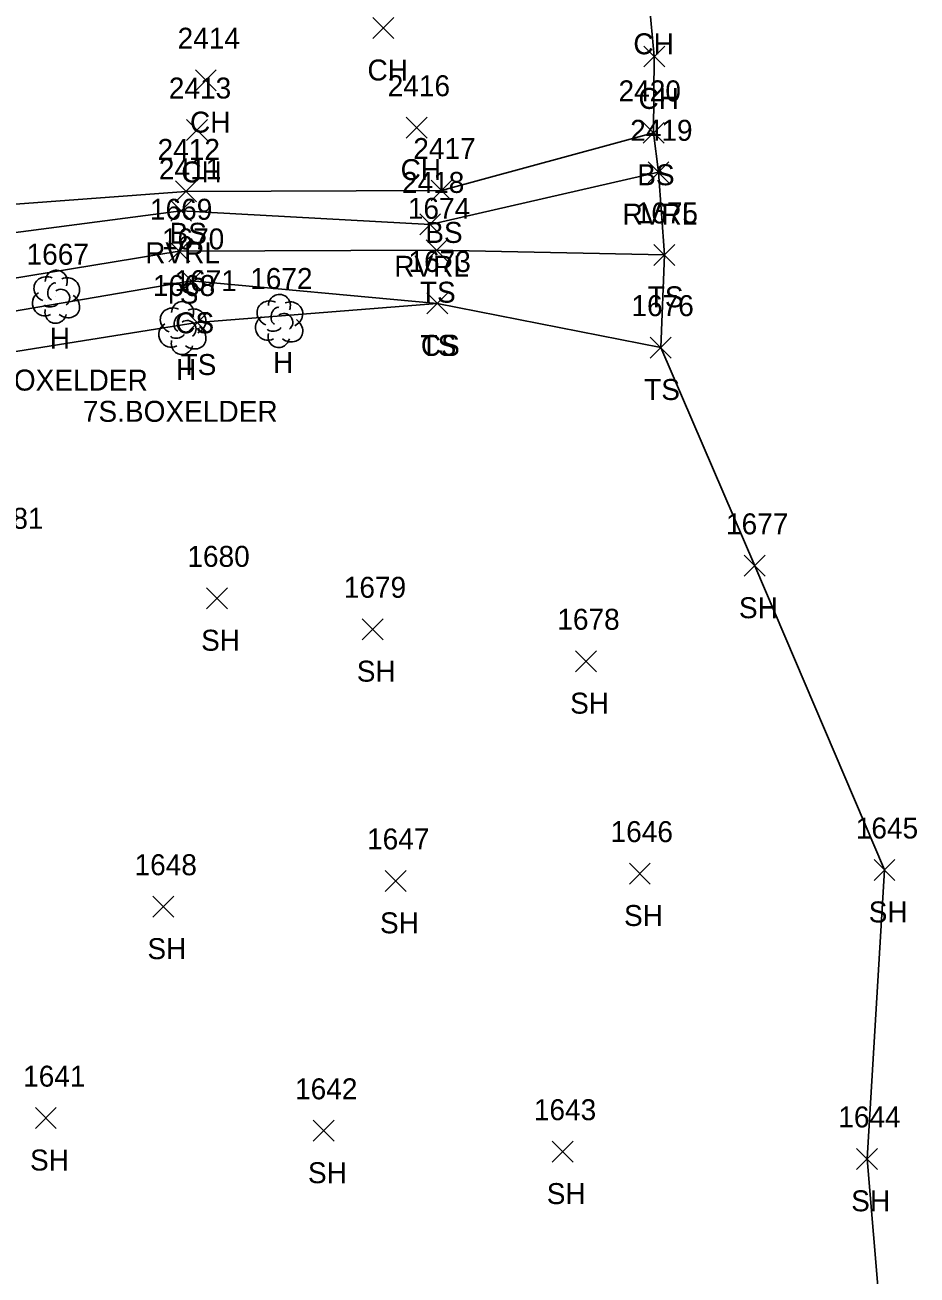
# Model space of a CAD drawing. Extents: x 1459992 to 1461532, y 647785 to 648535.
# Drawn here: x 1461426 to 1461511, y 648237.3 to 648356.5 of the extents above; entities that cross this region are included whole.
import ezdxf

# ---------------------------------------------------------------- set-up
doc = ezdxf.new("R2010")
doc.units = 0
for name, color, linetype in [('L_A', 7, 'Continuous'), ('L_C', 7, 'Continuous'), ('L_I', 7, 'Continuous'), ('L_TIC', 7, 'Continuous'), ('LAWE', 7, 'Continuous'), ('LELB', 7, 'Continuous'), ('LSOGP', 7, 'Continuous'), ('LTD', 7, 'Continuous')]:
    doc.layers.add(name, color=color, linetype=linetype)

msp = doc.modelspace()

# ---------------------------------------------------------------- linework, layer by layer
at = {"layer": 'L_TIC'}
for points in [[(1461459.14, 648355.22), (1461461.14, 648357.22)], [(1461461.14, 648355.22), (1461459.14, 648357.22)], [(1461484.99, 648352.51), (1461486.99, 648354.51)], [(1461486.99, 648352.51), (1461484.99, 648354.51)], [(1461442.21, 648350.25), (1461444.21, 648352.25)], [(1461444.21, 648350.25), (1461442.21, 648352.25)], [(1461441.38, 648345.5), (1461443.38, 648347.5)], [(1461443.38, 648345.5), (1461441.38, 648347.5)], [(1461462.31, 648345.72), (1461464.31, 648347.72)], [(1461464.31, 648345.72), (1461462.31, 648347.72)], [(1461484.92, 648345.23), (1461486.92, 648347.23)], [(1461486.92, 648345.23), (1461484.92, 648347.23)], [(1461485.39, 648341.47), (1461487.39, 648343.47)], [(1461487.39, 648341.47), (1461485.39, 648343.47)], [(1461440.31, 648339.65), (1461442.31, 648341.65)], [(1461442.31, 648339.65), (1461440.31, 648341.65)], [(1461464.69, 648339.73), (1461466.69, 648341.73)], [(1461466.69, 648339.73), (1461464.69, 648341.73)], [(1461439.86, 648337.79), (1461441.86, 648339.79)], [(1461441.86, 648337.79), (1461439.86, 648339.79)], [(1461463.61, 648336.5), (1461465.61, 648338.5)], [(1461465.61, 648336.5), (1461463.61, 648338.5)], [(1461464.22, 648334.03), (1461466.22, 648336.03)], [(1461466.22, 648334.03), (1461464.22, 648336.03)], [(1461439.68, 648333.94), (1461441.68, 648335.94)], [(1461441.68, 648333.94), (1461439.68, 648335.94)], [(1461485.95, 648333.59), (1461487.95, 648335.59)], [(1461487.95, 648333.59), (1461485.95, 648335.59)], [(1461440.85, 648331.11), (1461442.85, 648333.11)], [(1461442.85, 648331.11), (1461440.85, 648333.11)], [(1461464.28, 648328.96), (1461466.28, 648330.96)], [(1461466.28, 648328.96), (1461464.28, 648330.96)], [(1461464.28, 648328.96), (1461466.28, 648330.96)], [(1461466.28, 648328.96), (1461464.28, 648330.96)], [(1461441.39, 648327.13), (1461443.39, 648329.13)], [(1461443.39, 648327.13), (1461441.39, 648329.13)], [(1461485.61, 648324.75), (1461487.61, 648326.75)], [(1461487.61, 648324.75), (1461485.61, 648326.75)], [(1461494.57, 648303.94), (1461496.57, 648305.94)], [(1461496.57, 648303.94), (1461494.57, 648305.94)], [(1461443.27, 648300.84), (1461445.27, 648302.84)], [(1461445.27, 648300.84), (1461443.27, 648302.84)], [(1461458.12, 648297.89), (1461460.12, 648299.89)], [(1461460.12, 648297.89), (1461458.12, 648299.89)], [(1461478.48, 648294.84), (1461480.48, 648296.84)], [(1461480.48, 648294.84), (1461478.48, 648296.84)], [(1461483.61, 648274.59), (1461485.61, 648276.59)], [(1461485.61, 648274.59), (1461483.61, 648276.59)], [(1461506.95, 648274.93), (1461508.95, 648276.93)], [(1461508.95, 648274.93), (1461506.95, 648276.93)], [(1461460.33, 648273.89), (1461462.33, 648275.89)], [(1461462.33, 648273.89), (1461460.33, 648275.89)], [(1461438.15, 648271.43), (1461440.15, 648273.43)], [(1461440.15, 648271.43), (1461438.15, 648273.43)], [(1461426.95, 648251.27), (1461428.95, 648253.27)], [(1461428.95, 648251.27), (1461426.95, 648253.27)], [(1461453.46, 648250.06), (1461455.46, 648252.06)], [(1461455.46, 648250.06), (1461453.46, 648252.06)], [(1461476.24, 648248.07), (1461478.24, 648250.07)], [(1461478.24, 648248.07), (1461476.24, 648250.07)], [(1461505.28, 648247.38), (1461507.28, 648249.38)], [(1461507.28, 648247.38), (1461505.28, 648249.38)]]:
    msp.add_lwpolyline(points, dxfattribs=at)
at = {"layer": 'LAWE'}
msp.add_lwpolyline([(1461220.16, 648021.62), (1461235.47, 648039.29), (1461252.97, 648048.33), (1461267.66, 648064.22), (1461276.22, 648071.52), (1461288.83, 648087.7), (1461307.75, 648107.55), (1461316.99, 648127.78), (1461326.45, 648138.79), (1461334.87, 648155.88), (1461340.57, 648163.3), (1461349.8, 648178.34), (1461354.71, 648199.54), (1461353.8, 648220.98), (1461352.34, 648246.45), (1461354.08, 648262.22), (1461358.25, 648276.14), (1461371.39, 648295.38), (1461381.98, 648319.02), (1461394.18, 648330.62), (1461418.25, 648335.82), (1461440.86, 648338.79), (1461464.61, 648337.5), (1461486.39, 648342.47)], dxfattribs=at)
at = {"layer": 'LELB'}
for points in [[(1461216.74, 648025.38), (1461232.53, 648043.68), (1461249.11, 648052.7), (1461265.41, 648068.57), (1461273.18, 648074.77), (1461285.77, 648090.04), (1461304, 648110.19), (1461314.1, 648129.87), (1461321.79, 648141.88), (1461329.36, 648157.89), (1461338.08, 648167.02), (1461343.94, 648182.36), (1461347.49, 648202.69), (1461348.84, 648222.98), (1461349.52, 648245.94), (1461349.95, 648262.88), (1461353.5, 648277.37), (1461366.77, 648299.23), (1461380.28, 648319.06), (1461391.62, 648332.95), (1461418.6, 648338.96), (1461441.31, 648340.65), (1461465.69, 648340.73), (1461485.92, 648346.23)], [(1461358.31, 648179.35), (1461357.65, 648195.69), (1461360.6, 648216.92), (1461360.16, 648235.42), (1461360.99, 648255.36), (1461365.03, 648278.4), (1461376.07, 648295.04), (1461384.29, 648312.49), (1461396.99, 648324.63), (1461420.1, 648331.58), (1461440.68, 648334.94), (1461465.22, 648335.03), (1461486.95, 648334.59)], [(1461357.65, 648195.69), (1461372.62, 648210.83), (1461379.23, 648235), (1461368.44, 648254), (1461374.32, 648275.06), (1461388.08, 648297.08), (1461390.71, 648303.65), (1461401.54, 648316.28), (1461420.08, 648328.39), (1461441.85, 648332.11), (1461465.28, 648329.96)], [(1461372.62, 648210.83), (1461395.44, 648232.26), (1461377.27, 648257.09), (1461379.78, 648272.05), (1461393.46, 648294.26), (1461394.35, 648300.85), (1461403.62, 648312.48), (1461422.06, 648324.89), (1461442.39, 648328.13), (1461465.28, 648329.96), (1461486.61, 648325.75)]]:
    msp.add_lwpolyline(points, dxfattribs=at)
at = {"layer": 'LSOGP'}
msp.add_lwpolyline([(1461508.15, 648226.37), (1461506.28, 648248.38), (1461507.95, 648275.93), (1461495.57, 648304.94), (1461486.61, 648325.75), (1461486.95, 648334.59), (1461486.39, 648342.47), (1461485.92, 648346.23), (1461485.99, 648353.51), (1461485.5, 648358.72)], dxfattribs=at)
at = {"layer": 'LTD'}
for p, q in [((1461428.9, 648330.65), (1461428.9, 648330.65)), ((1461428.9, 648330.65), (1461428.9, 648330.65)), ((1461440.95, 648327.67), (1461440.95, 648327.67)), ((1461440.95, 648327.67), (1461440.95, 648327.67)), ((1461450.18, 648328.34), (1461450.18, 648328.34)), ((1461450.18, 648328.34), (1461450.18, 648328.34))]:
    msp.add_line(p, q, dxfattribs=at)
for centre in [(1461428.95, 648332.08), (1461441, 648329.1), (1461450.23, 648329.77)]:
    msp.add_arc(centre, 1.05, 335.5272, 180.9563, dxfattribs=at)
for centre, major_axis, ratio, start_param, end_param in [((1461428.11, 648331.31), (1.21, -0.51), 0.895232, 1.570796, 4.712389), ((1461429.94, 648331.23), (-1.14, -0.48), 0.949671, 1.570796, 4.712389), ((1461428.69, 648331.11), (-0.208, -0.792), 0.645439, 3.141593, 6.283185), ((1461429.4, 648330.48), (-0.5, 0.667), 0.989748, 3.141593, 6.283185), ((1461427.82, 648329.94), (0.58, -1.04), 0.959034, 3.141593, 6.283185), ((1461429.9, 648329.81), (-1.09, 0.79), 0.841452, 1.570796, 4.712389), ((1461449.39, 648329), (1.21, -0.51), 0.895232, 1.570796, 4.712389), ((1461451.23, 648328.92), (-1.14, -0.48), 0.949671, 1.570796, 4.712389), ((1461428.9, 648329.15), (0.26, 1.06), 0.942809, 1.570796, 4.712389), ((1461428.44, 648329.9), (-0.625, -0.083), 0.423636, 0, 3.141593), ((1461440.16, 648328.33), (1.21, -0.51), 0.895232, 1.570796, 4.712389), ((1461440.74, 648328.12), (-0.208, -0.792), 0.645439, 3.141593, 6.283185), ((1461441.99, 648328.25), (-1.14, -0.48), 0.949671, 1.570796, 4.712389), ((1461449.98, 648328.79), (-0.208, -0.792), 0.645439, 3.141593, 6.283185), ((1461450.68, 648328.17), (-0.5, 0.667), 0.989748, 3.141593, 6.283185), ((1461439.87, 648326.96), (0.58, -1.04), 0.959034, 3.141593, 6.283185), ((1461441.45, 648327.5), (-0.5, 0.667), 0.989748, 3.141593, 6.283185), ((1461441.95, 648326.83), (-1.09, 0.79), 0.841452, 1.570796, 4.712389), ((1461449.1, 648327.63), (0.58, -1.04), 0.959034, 3.141593, 6.283185), ((1461449.73, 648327.59), (-0.625, -0.083), 0.423636, 0, 3.141593), ((1461451.18, 648327.5), (-1.09, 0.79), 0.841452, 1.570796, 4.712389), ((1461440.49, 648326.92), (-0.625, -0.083), 0.423636, 0, 3.141593), ((1461450.18, 648326.84), (0.26, 1.06), 0.942809, 1.570796, 4.712389), ((1461440.95, 648326.17), (0.26, 1.06), 0.942809, 1.570796, 4.712389)]:
    msp.add_ellipse(centre, major_axis=major_axis, ratio=ratio, start_param=start_param, end_param=end_param, dxfattribs=at)

# ---------------------------------------------------------------- texts
at = {"layer": 'L_A'}
for s, p in [('CH', (1461483.99, 648353.72)), ('CH', (1461458.63, 648351.22)), ('CH', (1461484.48, 648348.51)), ('CH', (1461441.7, 648346.25)), ('CH', (1461440.87, 648341.5)), ('CH', (1461461.79, 648341.72)), ('BS', (1461484.36, 648341.23)), ('RVRL', (1461482.96, 648337.47)), ('BS', (1461439.75, 648335.65)), ('BS', (1461464.14, 648335.73)), ('RVRL', (1461437.43, 648333.79)), ('RVRL', (1461461.18, 648332.5)), ('TS', (1461439.09, 648329.94)), ('TS', (1461463.63, 648330.03)), ('TS', (1461485.36, 648329.59)), ('CS', (1461440.29, 648327.11)), ('H', (1461428.33, 648325.65)), ('TS', (1461463.69, 648324.96)), ('CS', (1461463.72, 648324.96)), ('H', (1461449.62, 648323.34)), ('H', (1461440.38, 648322.67)), ('TS', (1461440.8, 648323.13)), ('TS', (1461485.02, 648320.75)), ('SH', (1461494.06, 648299.94)), ('SH', (1461442.76, 648296.84)), ('SH', (1461457.61, 648293.89)), ('SH', (1461477.96, 648290.84)), ('SH', (1461506.44, 648270.93)), ('SH', (1461459.82, 648269.89)), ('SH', (1461483.1, 648270.59)), ('SH', (1461437.64, 648267.43)), ('SH', (1461426.44, 648247.27)), ('SH', (1461452.95, 648246.06)), ('SH', (1461475.73, 648244.07)), ('SH', (1461504.77, 648243.38))]:
    msp.add_text(s, height=2, dxfattribs=at).set_placement(p)
at = {"layer": 'L_C'}
for s, p in [('S. BOXELDER', (1461419.84, 648321.65)), ('7S.BOXELDER', (1461431.48, 648318.67))]:
    msp.add_text(s, height=2, dxfattribs=at).set_placement(p)
at = {"layer": 'L_I'}
for s, p in [('2414', (1461440.52, 648354.25)), ('2413', (1461439.68, 648349.5)), ('2416', (1461460.56, 648349.72)), ('2420', (1461482.58, 648349.23)), ('2419', (1461483.69, 648345.47)), ('2412', (1461438.61, 648343.65)), ('2417', (1461463, 648343.73)), ('2411', (1461438.73, 648341.79)), ('2418', (1461461.92, 648340.5)), ('1669', (1461437.88, 648337.94)), ('1674', (1461462.48, 648338.03)), ('1675', (1461484.21, 648337.59)), ('1670', (1461439.02, 648335.11)), ('1667', (1461426.11, 648333.65)), ('1673', (1461462.54, 648332.96)), ('1673', (1461462.54, 648332.96)), ('1668', (1461438.16, 648330.67)), ('1671', (1461440.22, 648331.13)), ('1672', (1461447.44, 648331.34)), ('1676', (1461483.81, 648328.75)), ('1681', (1461421.78, 648308.47)), ('1677', (1461492.83, 648307.94)), ('1680', (1461441.45, 648304.84)), ('1679', (1461456.37, 648301.89)), ('1678', (1461476.74, 648298.84)), ('1646', (1461481.82, 648278.59)), ('1645', (1461505.21, 648278.93)), ('1647', (1461458.59, 648277.89)), ('1648', (1461436.41, 648275.43)), ('1641', (1461425.78, 648255.27)), ('1642', (1461451.72, 648254.06)), ('1643', (1461474.5, 648252.07)), ('1644', (1461503.54, 648251.38))]:
    msp.add_text(s, height=2, dxfattribs=at).set_placement(p)

doc.saveas('drawing.dxf')
